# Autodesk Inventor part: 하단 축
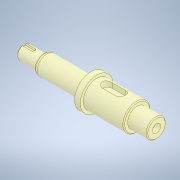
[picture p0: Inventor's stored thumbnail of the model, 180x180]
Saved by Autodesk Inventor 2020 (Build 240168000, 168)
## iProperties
Created: 2024-05
Part Number: 하단 축
Material: 강철, 탄소
Document SubType Name: Modeling
Designer: oem
Density: 7.85 g/cm^3
Appearance: 기본값
Author: jhkim
Sending System: Autodesk Inventor 2025
Preprocessor: ST-DEVELOPER v20
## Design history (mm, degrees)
feature "솔리드1"
node "솔리드2"
